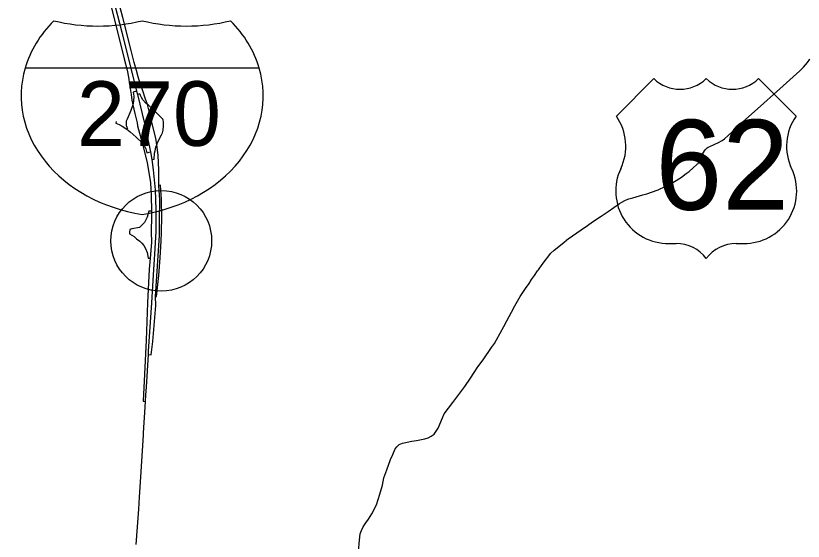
# Model space of a CAD drawing. Extents: x 0 to 34, y 0 to 22.
# Drawn here: x 6.761 to 7.89, y 18.155 to 18.908 of the extents above; entities that cross this region are included whole.
import ezdxf

# ---------------------------------------------------------------- set-up
doc = ezdxf.new("R2010")
doc.units = 0
for name, color, linetype in [('GM_X_Interchange_Ramps', 7, 'Continuous'), ('GM_X_Interstate_Route', 7, 'Continuous'), ('GM_X_Interstate_Shield', 7, 'Continuous'), ('GM_X_US_Route', 7, 'Continuous'), ('GM_X_US_Shield', 7, 'Continuous'), ('SH_Text', 7, 'Continuous')]:
    doc.layers.add(name, color=color, linetype=linetype)

msp = doc.modelspace()

# ---------------------------------------------------------------- linework, layer by layer
at = {"layer": 'GM_X_Interchange_Ramps'}
for points in [[(6.8923, 18.9419), (6.9032, 18.8985), (6.9164, 18.8463), (6.9204, 18.83), (6.9224, 18.8198), (6.9241, 18.8097), (6.9261, 18.7953), (6.9274, 18.7868), (6.9286, 18.7804), (6.9314, 18.7681), (6.9347, 18.7544), (6.9355, 18.7502), (6.942, 18.7261), (6.9492, 18.6975), (6.9541, 18.6684), (6.9549, 18.6506), (6.9554, 18.6279), (6.9556, 18.6205), (6.9549, 18.5989), (6.9554, 18.583), (6.9535, 18.5606), (6.9522, 18.5447), (6.9496, 18.4969), (6.9478, 18.443), (6.9454, 18.3943), (6.9434, 18.3556), (6.9465, 18.3554)], [(6.9505, 18.4224), (6.9552, 18.4221), (6.9573, 18.4415), (6.9616, 18.493), (6.961, 18.5058), (6.9668, 18.5929), (6.9668, 18.5989), (6.967, 18.6103), (6.9673, 18.6442), (6.9659, 18.665), (6.9658, 18.6866), (6.9652, 18.7084), (6.9631, 18.7231), (6.9615, 18.7325), (6.9564, 18.7531), (6.9531, 18.7675), (6.9496, 18.7809), (6.9466, 18.7898), (6.943, 18.8004), (6.9387, 18.8125), (6.9363, 18.8207), (6.9339, 18.8294), (6.9305, 18.8411), (6.9263, 18.8584), (6.9142, 18.9055), (6.9076, 18.9307)], [(6.9341, 18.8), (6.9294, 18.7987), (6.93, 18.7927), (6.9299, 18.7858), (6.9293, 18.7825), (6.9286, 18.7804), (6.9257, 18.7724), (6.9208, 18.7596), (6.9193, 18.7571), (6.9192, 18.7554)], [(6.9727, 18.7522), (6.9727, 18.7537), (6.9726, 18.7566), (6.9721, 18.7583), (6.9716, 18.7596), (6.9708, 18.7607), (6.9694, 18.7622), (6.9664, 18.765), (6.951, 18.7797), (6.9496, 18.7809), (6.9475, 18.7827), (6.9432, 18.7875), (6.9413, 18.7909), (6.9399, 18.7937), (6.9389, 18.7961), (6.9353, 18.7953)], [(6.9046, 18.7566), (6.9044, 18.7539), (6.909, 18.7522), (6.9134, 18.75), (6.9202, 18.7456), (6.9251, 18.7418), (6.9337, 18.7338), (6.942, 18.7261), (6.9443, 18.723), (6.9472, 18.7175), (6.9489, 18.7118), (6.9538, 18.7129)], [(6.9192, 18.7554), (6.9191, 18.7543), (6.919, 18.7524), (6.9191, 18.7509), (6.9194, 18.7496), (6.9201, 18.7482), (6.921, 18.7465), (6.9202, 18.7456)], [(6.9559, 18.7021), (6.9593, 18.7025), (6.96, 18.7109), (6.9605, 18.7143), (6.9619, 18.7196), (6.9631, 18.7231), (6.9643, 18.7263), (6.9665, 18.7308), (6.9681, 18.7339), (6.97, 18.7375), (6.9711, 18.7403), (6.972, 18.7441), (6.9726, 18.7503), (6.9727, 18.7522)], [(6.97, 18.5988), (6.97, 18.6004), (6.9704, 18.6182), (6.9699, 18.6448), (6.9686, 18.6653), (6.9659, 18.665)], [(6.9554, 18.6279), (6.9515, 18.6279), (6.9494, 18.6194), (6.9453, 18.612), (6.9381, 18.6045), (6.9275, 18.6026), (6.9242, 18.6018), (6.924, 18.5977)], [(6.924, 18.5977), (6.9239, 18.5957), (6.9274, 18.5938), (6.9306, 18.5916), (6.9342, 18.5883), (6.9389, 18.5851), (6.9415, 18.5823), (6.9443, 18.5786), (6.9468, 18.5744), (6.9493, 18.5689), (6.9509, 18.5605), (6.9535, 18.5606)], [(6.961, 18.5058), (6.9627, 18.5058), (6.9659, 18.5357), (6.968, 18.5611), (6.9695, 18.5855), (6.9699, 18.597), (6.97, 18.5988)]]:
    msp.add_lwpolyline(points, dxfattribs=at)
at = {"layer": 'GM_X_Interstate_Route'}
for points in [[(6.8982, 18.9425), (6.8983, 18.9422), (6.9034, 18.9214), (6.9095, 18.8974)], [(6.9095, 18.8974), (6.9128, 18.8845), (6.9341, 18.8), (6.9353, 18.7953), (6.9453, 18.7537)], [(6.9453, 18.7537), (6.9503, 18.7305), (6.9538, 18.7129), (6.9559, 18.7021), (6.958, 18.687), (6.9606, 18.6588), (6.9617, 18.6302), (6.9616, 18.5989), (6.9596, 18.5662), (6.9577, 18.5367), (6.9556, 18.4968), (6.9509, 18.4273)], [(6.9509, 18.4273), (6.9505, 18.4224), (6.9476, 18.3758), (6.947, 18.365)], [(6.947, 18.365), (6.9465, 18.3554), (6.946, 18.3471)], [(6.946, 18.3471), (6.9436, 18.3106)], [(6.9436, 18.3106), (6.9433, 18.3071), (6.9397, 18.2474)], [(6.9397, 18.2474), (6.9379, 18.2183)], [(6.9379, 18.2183), (6.9369, 18.2009), (6.9332, 18.1502)]]:
    msp.add_lwpolyline(points, dxfattribs=at)
at = {"layer": 'GM_X_Interstate_Shield'}
msp.add_line((7.1099, 18.8328), (6.7743, 18.8328), dxfattribs=at)
msp.add_line((7.1099, 18.8328), (6.7743, 18.8328), dxfattribs=at)
for centre, start_param, end_param in [((6.9855, 18.7932), 2.47259, 2.911027), ((6.8787, 19.0668), 4.415841, 5.008937), ((7.0055, 19.0668), 4.415841, 5.008937), ((6.8987, 18.7932), 0.230566, 0.669003), ((6.9855, 18.7932), 2.911027, 4.511031), ((6.8987, 18.7932), 4.913747, 6.513751)]:
    msp.add_ellipse(centre, major_axis=(0.2169, 0), ratio=0.8, start_param=start_param, end_param=end_param, dxfattribs=at)
at = {"layer": 'GM_X_US_Route'}
for points in [[(7.7998, 18.7526), (7.8033, 18.7559), (7.8241, 18.7748), (7.856, 18.8034), (7.8846, 18.829), (7.8903, 18.8342), (7.8959, 18.8412), (7.899, 18.8456), (7.8991, 18.846)], [(7.7724, 18.7286), (7.7734, 18.7291), (7.7766, 18.7317), (7.7823, 18.7363), (7.7998, 18.7526)], [(7.7681, 18.7263), (7.7693, 18.7268), (7.7724, 18.7286)], [(7.7454, 18.7095), (7.7483, 18.7144), (7.7492, 18.7159), (7.7504, 18.7173), (7.7519, 18.7187), (7.7533, 18.7196), (7.7557, 18.7207), (7.7618, 18.7234), (7.7681, 18.7263)], [(7.7454, 18.7095), (7.7446, 18.7099), (7.7436, 18.71), (7.7427, 18.7099), (7.7416, 18.7094), (7.7407, 18.7089), (7.7401, 18.7083), (7.7392, 18.707), (7.739, 18.7056), (7.739, 18.7046)], [(7.745, 18.7017), (7.7452, 18.7019), (7.7465, 18.7033), (7.7469, 18.704), (7.7471, 18.7055)], [(7.7471, 18.7055), (7.7471, 18.7055), (7.747, 18.7067), (7.7468, 18.7078), (7.7465, 18.7086), (7.7454, 18.7095)], [(7.722, 18.6818), (7.7262, 18.685), (7.7319, 18.6902), (7.7371, 18.6947), (7.7381, 18.6956), (7.7389, 18.6965), (7.7399, 18.6982), (7.7408, 18.7002)], [(7.739, 18.7046), (7.739, 18.7045), (7.7393, 18.7036), (7.7398, 18.7024)], [(7.7398, 18.7024), (7.7398, 18.7022), (7.7408, 18.7002)], [(7.7408, 18.7002), (7.7429, 18.7005), (7.7442, 18.7012), (7.745, 18.7017)], [(7.6891, 18.6617), (7.6991, 18.6666), (7.7077, 18.6717), (7.7152, 18.6767), (7.722, 18.6818)], [(7.6101, 18.6277), (7.6263, 18.6389), (7.6299, 18.6411), (7.634, 18.6434), (7.6381, 18.6451), (7.6397, 18.6455), (7.6454, 18.6473), (7.6597, 18.6514), (7.6656, 18.653), (7.6723, 18.6551), (7.6818, 18.6585), (7.6847, 18.6598)], [(7.6847, 18.6598), (7.6891, 18.6617)], [(7.5878, 18.6125), (7.6002, 18.6208), (7.6101, 18.6277)], [(7.5714, 18.6013), (7.5803, 18.6075), (7.5878, 18.6125)], [(7.5571, 18.5913), (7.5591, 18.5928)], [(7.5591, 18.5928), (7.5714, 18.6013)], [(7.5045, 18.536), (7.5089, 18.5425), (7.51, 18.5441), (7.5155, 18.5515), (7.5215, 18.5598), (7.5281, 18.5676), (7.5329, 18.572), (7.544, 18.5812), (7.5531, 18.5886), (7.5571, 18.5913)], [(7.5003, 18.5299), (7.5045, 18.536)], [(7.4647, 18.4709), (7.4713, 18.4834), (7.4761, 18.4923), (7.4841, 18.5059), (7.4917, 18.5171), (7.4967, 18.5244), (7.5003, 18.5299)], [(7.3105, 18.2935), (7.3151, 18.2958), (7.3287, 18.2983), (7.3351, 18.2992), (7.3472, 18.3016), (7.352, 18.3032), (7.3565, 18.3056), (7.3605, 18.3087), (7.3663, 18.3171), (7.3725, 18.332), (7.3752, 18.3378), (7.3874, 18.3537), (7.3945, 18.3634), (7.4047, 18.377), (7.4125, 18.3887), (7.4234, 18.4049), (7.4308, 18.4149), (7.443, 18.4327), (7.447, 18.4385), (7.4501, 18.4438), (7.4603, 18.4628), (7.4647, 18.4709)], [(7.2548, 18.1655), (7.2563, 18.1703), (7.2587, 18.1755), (7.2629, 18.1814), (7.2664, 18.1865), (7.2713, 18.1945), (7.2778, 18.2071), (7.2828, 18.2223), (7.2867, 18.2356), (7.2887, 18.2461), (7.2926, 18.2575), (7.2982, 18.2724), (7.3012, 18.2795), (7.3049, 18.2877), (7.3071, 18.2905), (7.3105, 18.2935)], [(7.2512, 18.1059), (7.2517, 18.1226), (7.2522, 18.1402), (7.2535, 18.1566), (7.2548, 18.1655)]]:
    msp.add_lwpolyline(points, dxfattribs=at)
at = {"layer": 'GM_X_US_Shield'}
for p, q in [((7.6754, 18.8179), (7.6218, 18.7642)), ((7.8795, 18.7642), (7.8258, 18.8179)), ((7.6969, 18.5817), (7.7077, 18.5817)), ((7.7936, 18.5817), (7.8043, 18.5817))]:
    msp.add_line(p, q, dxfattribs=at)
for centre, radius, start, end in [((7.713, 18.8563), 0.0537, 225.573, 314.427), ((7.7882, 18.8563), 0.0537, 225.573, 314.427), ((7.5602, 18.7211), 0.0752, 334.5471, 35.0009), ((7.941, 18.7211), 0.0752, 144.9991, 205.4529), ((7.6961, 18.6569), 0.0752, 154.8319, 270.6383), ((7.8051, 18.6569), 0.0752, 269.3617, 25.1681), ((7.7077, 18.528), 0.0537, 36.8699, 90), ((7.7936, 18.528), 0.0537, 90, 143.1301)]:
    msp.add_arc(centre, radius, start, end, dxfattribs=at)
at = {"layer": 'SH_Text'}
msp.add_circle((6.9695, 18.5855), 0.0722, dxfattribs=at)

# ---------------------------------------------------------------- texts
at = {"layer": 'GM_X_Interstate_Shield'}
msp.add_text('270', height=0.09255, dxfattribs=at).set_placement((6.8486, 18.7215))
at = {"layer": 'GM_X_US_Shield'}
msp.add_text('62', height=0.12885, dxfattribs=at).set_placement((7.6777, 18.63))

doc.saveas('drawing.dxf')
